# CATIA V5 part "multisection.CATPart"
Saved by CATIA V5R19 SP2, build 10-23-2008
Part number: Part2
Bounding box of the stored display mesh (mm): x -19.918 to 19.548, y -0.039 to 80.56, z -11.729 to 30.512
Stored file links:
  D:\Catia fórum\Modely - Otazky\Roura - profil\multisection.CATPart
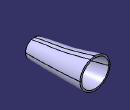
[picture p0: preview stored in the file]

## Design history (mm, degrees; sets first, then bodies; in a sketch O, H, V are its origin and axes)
AxisSystem1: origin (0, 0, 0), X (1, 0, 0), Y (0, 1, 0), Z (0, 0, 1)
Set1
  Plane1: type Offset, RefPlane ZX plane of AxisSystem1, Offset 20
  Plane2: type Offset, RefPlane Plane1, Offset 20
  Plane3: type Offset, RefPlane Plane2, Offset 20
  Plane4: type Offset, RefPlane Plane3, Offset 20
  Sketch1 on zx-plane, origin (0, 0, 0), H (-1, 0, 0), V (0, 0, 1)
    circle A1 centre (0, 0) radius 11.7288
  Sketch2 on Plane1, origin (0, 20, 0), H (-1, 0, 0), V (0, 0, 1)
    circle A1 centre (0, 2.0866) radius 13.6054
    point P1 (0, 2.0866)
    coincidence: P1 V
  Sketch3 on Plane2, origin (0, 40, 0), H (-1, 0, 0), V (0, 0, 1)
    circle A1 centre (0, 4.2888) radius 15.1144
    point P1 (0, 4.2888)
    coincidence: P1 V
  Sketch4 on Plane3, origin (0, 60, 0), H (-1, 0, 0), V (0, 0, 1)
    circle A1 centre (0, 7.3281) radius 17.3157
    point P1 (0, 7.3281)
    coincidence: P1 V
  Sketch5 on Plane4, origin (0, 80, 0), H (-1, 0, 0), V (0, 0, 1)
    circle A1 centre (0.1854, 10.779) radius 19.7329
  Sketch6 on yz-plane, origin (0, 0, 0), H (0, 1, 0), V (0, 0, 1)
    projected line E1 (80, 30.512) -> (80, -8.9539) from Sketch5.A1
    point P1 (80, 30.512)
    projected line E2 (60, 24.6437) -> (60, -9.9876) from Sketch4.A1
    point P3 (60, 24.6437)
    projected line E3 (40, 19.4031) -> (40, -10.8256) from Sketch3.A1
    point P5 (40, 19.4031)
    projected line E4 (20, 15.692) -> (20, -11.5189) from Sketch2.A1
    point P7 (20, 15.692)
    projected line E5 (0, 11.7288) -> (0, -11.7288) from Sketch1.A1
    point P9 (0, 11.7288)
    spline S1 through (80, 30.512) (60, 24.6437) (40, 19.4031) (20, 15.692) (0, 11.7288)
    point P11 (80, 30.512)
    point P12 (60, 24.6437)
    point P13 (40, 19.4031)
    point P14 (20, 15.692)
    point P15 (0, 11.7288)
    coincidence: P11 P1, P12 P3, P13 P5, P14 P7, P15 P9
  Loft1: Sections (Sketch5; Sketch4; Sketch3; Sketch2; Sketch1), Guides Sketch6
Body1 (main body)
  ThickSurface1: Surface Loft1, TopOffset 2, BotOffset 0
